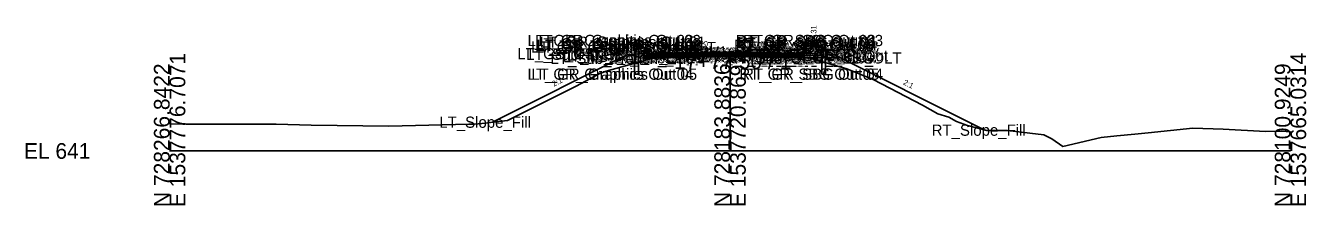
# Model space of a CAD drawing. Extents: x -26 to 1203, y -10 to 9522.
# Drawn here: x -25.7 to 202.8, y 8490.3 to 8522.3 of the extents above; entities that cross this region are included whole.
import ezdxf

# ---------------------------------------------------------------- set-up
doc = ezdxf.new("R2010")
doc.units = 0
for name, color, linetype in [('Default', 7, 'Continuous'), ('Exist Cross Section Cell', 7, 'Continuous'), ('Exist XS Center Line Elevation Label', 7, 'Continuous'), ('Exist XS Ground Line', 7, 'Continuous'), ('Old_Level_63', 7, 'Continuous'), ('Prop CMT Conc Surface', 7, 'Continuous'), ('Prop CMT Concrete Structures', 7, 'Continuous'), ('Prop CMT Guardrail Graphics', 7, 'Continuous'), ('Prop CMT Guardrail SBG', 7, 'Continuous'), ('Prop CMT Pvmt Course 1', 7, 'Continuous'), ('Prop CMT Pvmt Course 2', 7, 'Continuous'), ('Prop CMT Pvmt Course 3', 7, 'Continuous'), ('Prop CMT Pvmt Course SBG', 7, 'Continuous'), ('Prop CMT Pvmt Surface', 7, 'Continuous'), ('Prop CMT Pvmt Surface Overlay', 7, 'Continuous'), ('Prop CMT Pvmt Surface Shoulder', 7, 'Continuous'), ('Prop CMT Shld Paved Course 1', 7, 'Continuous'), ('Prop CMT Shld Paved Course 2', 7, 'Continuous'), ('Prop CMT Shld Paved Course 3', 7, 'Continuous'), ('Prop CMT Slope Grass', 7, 'Continuous'), ('Prop CMT Subgrade Earthwork', 7, 'Continuous'), ('Prop Superelevation  Arrow CELL', 7, 'Continuous'), ('Prop XS EOT Tick Mark', 7, 'Continuous'), ('Prop XS Hydro Elevations', 7, 'Continuous'), ('Prop XS SE Text', 7, 'Continuous'), ('Prop XS Side Slope Text', 7, 'Continuous')]:
    doc.layers.add(name, color=color, linetype=linetype)

msp = doc.modelspace()

# ---------------------------------------------------------------- linework, layer by layer
at = {"layer": 'Exist Cross Section Cell'}
for p, q in [((100, 8500), (100, 8517.4)), ((0, 8500), (100, 8500)), ((100, 8500), (200, 8500))]:
    msp.add_line(p, q, dxfattribs=at)
at = {"layer": 'Exist XS Ground Line'}
msp.add_lwpolyline([(0, 8504.86), (2.94, 8504.79), (10.38, 8504.76), (18.99, 8504.77), (25.23, 8504.57), (39.09, 8504.41), (53.42, 8504.75), (54.39, 8504.8), (55.69, 8504.92), (60.3, 8505.42), (72.54, 8511.52), (76.67, 8513.76), (77.9, 8514.22), (86.91, 8516.69), (87.92, 8516.79), (89.51, 8516.81), (100, 8516.93), (100.37, 8516.93), (109.91, 8516.82), (111.59, 8516.79), (113.9, 8516.68), (120.82, 8514.66), (125.54, 8512.72), (134.34, 8508.16), (137.06, 8506.64), (139.05, 8506.01), (140.39, 8505.27), (142.37, 8504.54), (145.81, 8503.63), (149.32, 8503.65), (149.51, 8503.64), (155.97, 8502.89), (157.41, 8502.15), (159.4, 8500.8), (166.24, 8502.4), (169.04, 8502.72), (172.23, 8502.97), (174.61, 8503.23), (182.57, 8504.06), (188.01, 8503.9), (195.55, 8503.48), (198.44, 8503.51), (200, 8503.42), (200, 8503.42)], dxfattribs=at)
at = {"layer": 'Prop CMT Conc Surface'}
msp.add_lwpolyline([(113.09, 8517.4), (115.42, 8517.31), (116.09, 8517.65)], dxfattribs=at)
at = {"layer": 'Prop CMT Concrete Structures'}
for points in [[(113.09, 8517.4), (115.42, 8517.31), (116.09, 8517.65)], [(116.09, 8517.65), (116.09, 8516.99)], [(113.09, 8516.99), (113.09, 8517.4)], [(116.09, 8516.99), (113.09, 8516.99)]]:
    msp.add_lwpolyline(points, dxfattribs=at)
at = {"layer": 'Prop CMT Guardrail Graphics'}
for points in [[(82.98, 8513.69), (82.98, 8519.69)], [(82.98, 8519.69), (84.31, 8519.69), (84.58, 8519.4)], [(84.58, 8518.81), (84.31, 8518.52), (83.64, 8518.52)], [(83.64, 8518.52), (83.64, 8513.69)], [(84.58, 8519.4), (84.31, 8519.1)], [(84.31, 8519.1), (84.58, 8518.81)], [(83.64, 8513.69), (82.98, 8513.69)]]:
    msp.add_lwpolyline(points, dxfattribs=at)
at = {"layer": 'Prop CMT Guardrail SBG'}
for points in [[(117.02, 8519.69), (115.69, 8519.69), (115.42, 8519.4)], [(115.42, 8519.4), (115.69, 8519.11)], [(115.69, 8519.11), (115.42, 8518.82)], [(115.42, 8518.82), (115.69, 8518.52), (116.36, 8518.52)], [(116.36, 8518.52), (116.36, 8513.69)], [(117.02, 8513.69), (117.02, 8519.69)], [(116.36, 8513.69), (117.02, 8513.69)]]:
    msp.add_lwpolyline(points, dxfattribs=at)
at = {"layer": 'Prop CMT Pvmt Course 1'}
for points in [[(100, 8517.67), (89, 8517.45)], [(89, 8517.45), (89, 8517.2)], [(89, 8517.2), (100, 8517.42)], [(100, 8517.42), (100, 8517.67)], [(100, 8517.67), (112, 8517.43)], [(100, 8517.42), (100, 8517.67)], [(100, 8517.42), (100, 8517.42), (100, 8517.42)], [(112, 8517.18), (100, 8517.42)], [(100, 8517.42), (100, 8517.42), (100, 8517.42)], [(112, 8517.43), (112, 8517.18)]]:
    msp.add_lwpolyline(points, dxfattribs=at)
at = {"layer": 'Prop CMT Pvmt Course 2'}
for points in [[(100, 8517.42), (89, 8517.2)], [(100, 8517.21), (100, 8517.42)], [(100, 8517.21), (100, 8517.42)], [(100, 8517.42), (112, 8517.18)], [(89, 8516.99), (100, 8517.21)], [(89, 8517.2), (89, 8516.99)], [(112, 8516.97), (100, 8517.21)], [(112, 8517.18), (112, 8516.97)]]:
    msp.add_lwpolyline(points, dxfattribs=at)
at = {"layer": 'Prop CMT Pvmt Course 3'}
for points in [[(100, 8517.21), (89, 8516.99)], [(89, 8516.99), (89, 8516.61)], [(89, 8516.61), (100, 8516.83)], [(100, 8516.83), (100, 8517.21)], [(100, 8517.21), (112, 8516.97)], [(100, 8516.83), (100, 8517.21)], [(112, 8516.59), (100, 8516.83)], [(112, 8516.97), (112, 8516.59)]]:
    msp.add_lwpolyline(points, dxfattribs=at)
at = {"layer": 'Prop CMT Pvmt Course SBG'}
for points in [[(113.09, 8516.99), (116.09, 8516.99), (116.59, 8516.99), (117, 8516.57)], [(113.09, 8516.57), (113.09, 8516.99)], [(117, 8516.57), (113.09, 8516.57)]]:
    msp.add_lwpolyline(points, dxfattribs=at)
at = {"layer": 'Prop CMT Pvmt Surface'}
for points in [[(100, 8517.67), (89, 8517.45)], [(100, 8517.67), (112, 8517.43)]]:
    msp.add_lwpolyline(points, dxfattribs=at)
at = {"layer": 'Prop CMT Pvmt Surface Overlay'}
for points in [[(100, 8517.67), (89, 8517.45)], [(100, 8517.67), (112, 8517.43)]]:
    msp.add_lwpolyline(points, dxfattribs=at)
at = {"layer": 'Prop CMT Pvmt Surface Shoulder'}
for points in [[(89, 8517.45), (84.62, 8517.36)], [(112, 8517.43), (113.09, 8517.4)]]:
    msp.add_lwpolyline(points, dxfattribs=at)
at = {"layer": 'Prop CMT Shld Paved Course 1'}
for points in [[(89, 8517.45), (84.62, 8517.36), (84.36, 8517.1)], [(89, 8517.2), (89, 8517.45)], [(112, 8517.43), (113.09, 8517.4)], [(112, 8517.18), (112, 8517.43)], [(84.36, 8517.1), (89, 8517.2)], [(113.09, 8517.15), (112, 8517.18)], [(113.09, 8517.4), (113.09, 8517.15)]]:
    msp.add_lwpolyline(points, dxfattribs=at)
at = {"layer": 'Prop CMT Shld Paved Course 2'}
for points in [[(89, 8517.2), (84.36, 8517.1), (84.15, 8516.89)], [(84.15, 8516.89), (89, 8516.99)], [(89, 8516.99), (89, 8517.2)], [(112, 8517.18), (113.09, 8517.15)], [(112, 8516.97), (112, 8517.18)], [(113.09, 8516.95), (112, 8516.97)], [(113.09, 8517.15), (113.09, 8516.95)]]:
    msp.add_lwpolyline(points, dxfattribs=at)
at = {"layer": 'Prop CMT Shld Paved Course 3'}
for points in [[(84.15, 8516.89), (83.77, 8516.51)], [(83.77, 8516.51), (89, 8516.61)], [(89, 8516.99), (84.15, 8516.89)], [(84.15, 8516.89), (84.15, 8516.89)], [(89, 8516.61), (89, 8516.99)], [(112, 8516.97), (113.09, 8516.95)], [(112, 8516.59), (112, 8516.97)], [(113.09, 8516.57), (112, 8516.59)], [(113.09, 8516.95), (113.09, 8516.57)]]:
    msp.add_lwpolyline(points, dxfattribs=at)
at = {"layer": 'Prop CMT Slope Grass'}
for points in [[(116.09, 8517.65), (116.84, 8518.04), (145.49, 8503.71)], [(81.58, 8517.11), (57.61, 8505.13)], [(84.58, 8517.35), (81.58, 8517.11)], [(84.62, 8517.36), (84.58, 8517.35)]]:
    msp.add_lwpolyline(points, dxfattribs=at)
at = {"layer": 'Prop CMT Subgrade Earthwork'}
for points in [[(83.77, 8516.51), (83.04, 8517.23)], [(89, 8516.61), (83.77, 8516.51)], [(100, 8516.83), (89, 8516.61)], [(100, 8516.83), (112, 8516.59)], [(112, 8516.59), (113.09, 8516.57)], [(113.09, 8516.57), (113.09, 8516.57)], [(113.09, 8516.57), (117, 8516.57), (119.78, 8516.57)]]:
    msp.add_lwpolyline(points, dxfattribs=at)
at = {"layer": 'Prop Superelevation  Arrow CELL'}
for p, q in [((96.81, 8518.22), (90.81, 8518.1)), ((103.51, 8518.11), (109.51, 8517.99))]:
    msp.add_line(p, q, dxfattribs=at)
for points in [[(90.81, 8518.1), (92.3, 8518.63), (91.97, 8518.12)], [(109.51, 8517.99), (108.02, 8518.52), (108.35, 8518.01)]]:
    msp.add_lwpolyline(points, close=True, dxfattribs=at)
at = {"layer": 'Prop XS EOT Tick Mark'}
for points in [[(89, 8517.45), (89, 8518.45)], [(112, 8517.43), (112, 8518.43)]]:
    msp.add_lwpolyline(points, dxfattribs=at)

# ---------------------------------------------------------------- texts
at = {"layer": 'Default'}
msp.add_text('-', height=0.0001, dxfattribs=at).set_placement((0, 8500))
msp.add_text('-', height=0.0001, dxfattribs=at).set_placement((0, 8500))
msp.add_text('-', height=0.0001, dxfattribs=at).set_placement((0, 8500))
at = {"layer": 'Exist Cross Section Cell'}
for s, p in [('L', (90, 8517.4)), ('17+77.50 / 1', (90, 8514.6)), ('EL 641', (-26, 8498.6))]:
    msp.add_text(s, height=2.8, dxfattribs=at).set_placement(p)
for s, p in [('N 728266.8422', (0, 8490)), ('E 1537776.7071', (2.8, 8490)), ('N 728183.8836', (100, 8490)), ('E 1537720.8692', (102.8, 8490)), ('N 728100.9249', (200, 8490)), ('E 1537665.0314', (202.8, 8490))]:
    msp.add_text(s, height=2.8, rotation=90, dxfattribs=at).set_placement(p)
at = {"layer": 'Exist XS Center Line Elevation Label'}
msp.add_text('657.93', height=0.75, dxfattribs=at).set_placement((98.37, 8515.87))
at = {"layer": 'Old_Level_63'}
for s, p in [('LT_GR_Graphics Out 03', (63.87, 8518.69)), ('LT_GR_Graphics Out 02', (65.21, 8518.69)), ('LT_GR_Graphics Out 09', (65.21, 8518.1)), ('LT_GR_Graphics Out 08', (65.48, 8517.81)), ('LT_GR_Graphics Out 01', (66.04, 8518.4)), ('RT_GR_SBG Out 08', (100.73, 8517.82)), ('RT_GR_SBG Out 02', (101, 8518.69)), ('RT_GR_SBG Out 09', (101, 8518.11)), ('RT_GR_SBG Out 01', (101.29, 8518.4)), ('RT_GR_SBG Out 03', (102.33, 8518.69)), ('LT_GS_OS_GR_Face_Graphics', (62.04, 8516.35)), ('LT_Sub_Trench_Out_DLT', (63.61, 8516.23)), ('LT_GR_Graphics Out 06', (64.49, 8517.52)), ('LT_GR_Graphics Out 07', (65.21, 8517.52)), ('LT_Sub_Trench_Out', (67.97, 8515.51)), ('LT_PS3_Shelf_Out', (70.13, 8515.89)), ('LT_GS_OS_CTL', (70.95, 8516.11)), ('LT_PS3_OEOP', (74.39, 8515.89)), ('LT_PS2_OEOP', (74.6, 8516.1)), ('LT_PS1_OEOP', (75.42, 8516.36)), ('LT_Sub_OEOT', (79.08, 8515.61)), ('LT_PV2_OEOT', (79.17, 8516.2)), ('LT_PV3_OEOT', (79.17, 8515.99)), ('LT_PV1_OEOT', (79.74, 8516.45)), ('LT_TM_OEOT', (79.94, 8517.45)), ('RT_PV1_OEEOP_W', (87.94, 8516.42)), ('LT_PV1_OEEOP_W', (87.98, 8516.42)), ('RT_Sub_OEEOP', (89.17, 8515.83)), ('LT_Sub_OEEOP', (89.21, 8515.83)), ('RT_PV2_OEEOP', (89.26, 8516.42)), ('RT_PV3_OEEOP', (89.26, 8516.21)), ('LT_PV2_OEEOP', (89.31, 8516.42)), ('LT_PV3_OEEOP', (89.31, 8516.21)), ('PV1_PGL_W', (92.58, 8516.42)), ('PV1_PGL', (94.47, 8516.67)), ('RT_Sub_OEOP_SBG', (99.5, 8515.57)), ('RT_SBG_C1 Shelf Out', (100.68, 8515.99)), ('RT_GR_SBG Out 07', (101, 8517.52)), ('RT_GR_SBG Out 06', (101.62, 8517.52)), ('RT_Sub_OEOT', (102.03, 8515.59)), ('RT_PV2_OEOT', (102.13, 8516.18)), ('RT_PV3_OEOT', (102.13, 8515.97)), ('RT_PV1_OEOT', (102.69, 8516.43)), ('RT_TM_OEOT', (102.9, 8517.43)), ('RT_CG_Bot_IE', (102.95, 8515.99)), ('RT_Sub_OEOP', (103.15, 8515.57)), ('RT_PS2_OEOP', (103.28, 8516.15)), ('RT_PS3_OEOP', (103.28, 8515.95)), ('RT_CG_Top_Gut', (103.61, 8516.31)), ('RT_PS1_OEOP', (103.84, 8516.4)), ('RT_Sub_SBG Out', (104.14, 8515.57)), ('RT_CG_Top_BOC', (104.32, 8516.65)), ('RT_CG_Bot_BOC', (104.35, 8515.99)), ('RT_GS_OS_CTL', (106.16, 8517.04)), ('RT_Sub_OSS_DLT', (107.13, 8515.57)), ('LT_GR_Graphics Out 04', (63.87, 8512.69)), ('LT_GR_Graphics Out 05', (64.54, 8512.69)), ('RT_GR_SBG Out 05', (101.66, 8512.69)), ('RT_GR_SBG Out 04', (102.33, 8512.69)), ('LT_Slope_Fill', (48.12, 8504.13)), ('RT_Slope_Fill', (135.97, 8502.71))]:
    msp.add_text(s, height=2, dxfattribs=at).set_placement(p)
at = {"layer": 'Prop XS Hydro Elevations'}
msp.add_text('658.31', height=1, rotation=90, dxfattribs=at).set_placement((115.42, 8518.31))
at = {"layer": 'Prop XS SE Text'}
for rotation, p in [(1.1458, (92.73, 8518.52)), (358.8542, (104.27, 8518.58))]:
    msp.add_text('0.020', height=1, rotation=rotation, dxfattribs=at).set_placement(p)
at = {"layer": 'Prop XS Side Slope Text'}
for rotation, p in [(26.5651, (68.55, 8511.44)), (333.4349, (130.79, 8511.9))]:
    msp.add_text('2:1', height=1, rotation=rotation, dxfattribs=at).set_placement(p)

doc.saveas('drawing.dxf')
